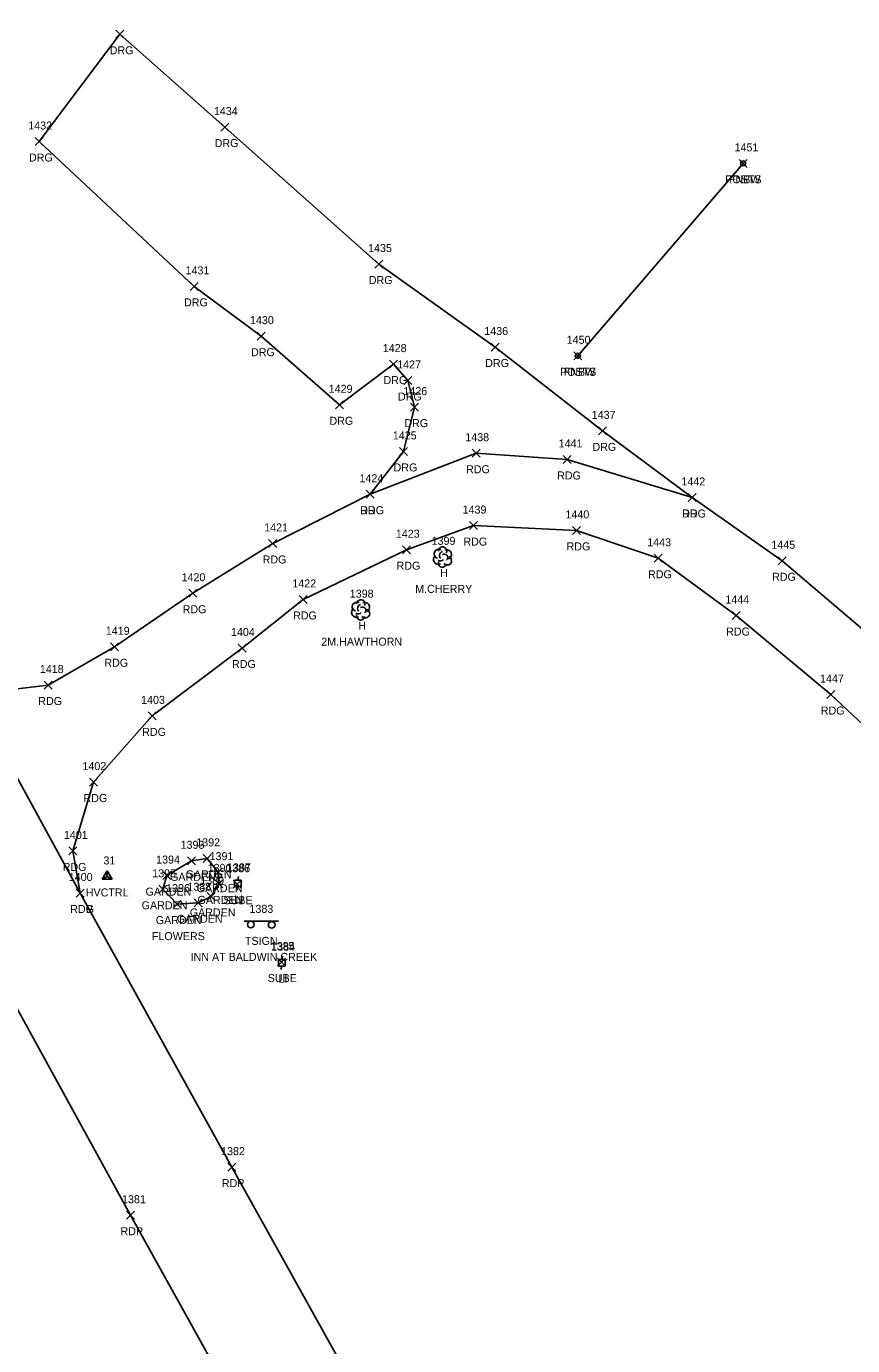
# Model space of a CAD drawing. Extents: x 1496556 to 1498241, y 599216 to 604470.
# Drawn here: x 1496878.1 to 1497084.6, y 603628.4 to 603958.1 of the extents above; entities that cross this region are included whole.
import ezdxf

# ---------------------------------------------------------------- set-up
doc = ezdxf.new("R2010")
doc.units = 0
for name, color, linetype in [('C_A', 7, 'Continuous'), ('C_I', 7, 'Continuous'), ('CPSM', 7, 'Continuous'), ('L_A', 7, 'Continuous'), ('L_C', 7, 'Continuous'), ('L_I', 7, 'Continuous'), ('L_TIC', 7, 'Continuous'), ('LAPB', 7, 'Continuous'), ('LFNC', 7, 'Continuous'), ('LPST', 7, 'Continuous'), ('LTD', 7, 'Continuous'), ('P_A', 7, 'Continuous'), ('P_I', 7, 'Continuous'), ('P_TIC', 7, 'Continuous'), ('PET', 7, 'Continuous'), ('PEU', 7, 'Continuous'), ('R_A', 7, 'Continuous'), ('R_I', 7, 'Continuous'), ('R_TIC', 7, 'Continuous'), ('RDG', 7, 'Continuous'), ('S_A', 7, 'Continuous'), ('S_C', 7, 'Continuous'), ('S_I', 7, 'Continuous'), ('SSGN', 7, 'Continuous'), ('U_A', 7, 'Continuous'), ('U_I', 7, 'Continuous'), ('U_TIC', 7, 'Continuous'), ('ULP', 7, 'Continuous')]:
    doc.layers.add(name, color=color, linetype=linetype)

msp = doc.modelspace()

# ---------------------------------------------------------------- linework, layer by layer
at = {"layer": 'CPSM'}
for p, q in [((1496896.96, 603744.93), (1496898.21, 603747.09)), ((1496896.96, 603744.93), (1496898.21, 603745.65)), ((1496899.46, 603744.93), (1496898.21, 603747.09)), ((1496898.21, 603745.65), (1496898.21, 603747.09)), ((1496898.21, 603745.65), (1496898.21, 603745.65)), ((1496898.21, 603745.65), (1496899.46, 603744.93)), ((1496896.96, 603744.93), (1496899.46, 603744.93))]:
    msp.add_line(p, q, dxfattribs=at)
at = {"layer": 'L_TIC'}
for points in [[(1497056.18, 603922.83), (1497058.18, 603924.83)], [(1497058.18, 603922.83), (1497056.18, 603924.83)], [(1497014.88, 603874.74), (1497016.88, 603876.74)], [(1497016.88, 603874.74), (1497014.88, 603876.74)], [(1496918.29, 603748.56), (1496920.29, 603750.56)], [(1496920.29, 603748.56), (1496918.29, 603750.56)], [(1496922.2, 603749.17), (1496924.2, 603751.17)], [(1496924.2, 603749.17), (1496922.2, 603751.17)], [(1496912.17, 603744.86), (1496914.17, 603746.86)], [(1496914.17, 603744.86), (1496912.17, 603746.86)], [(1496924.97, 603745.72), (1496926.97, 603747.72)], [(1496926.97, 603745.72), (1496924.97, 603747.72)], [(1496911.19, 603741.44), (1496913.19, 603743.44)], [(1496913.19, 603741.44), (1496911.19, 603743.44)], [(1496925.15, 603742.79), (1496927.15, 603744.79)], [(1496927.15, 603742.79), (1496925.15, 603744.79)], [(1496914.73, 603737.74), (1496916.73, 603739.74)], [(1496916.73, 603737.74), (1496914.73, 603739.74)], [(1496914.73, 603737.74), (1496916.73, 603739.74)], [(1496916.73, 603737.74), (1496914.73, 603739.74)], [(1496919.99, 603738.07), (1496921.99, 603740.07)], [(1496921.99, 603738.07), (1496919.99, 603740.07)], [(1496919.99, 603738.07), (1496921.99, 603740.07)], [(1496921.99, 603738.07), (1496919.99, 603740.07)], [(1496923.22, 603739.65), (1496925.22, 603741.65)], [(1496925.22, 603739.65), (1496923.22, 603741.65)]]:
    msp.add_lwpolyline(points, dxfattribs=at)
at = {"layer": 'LAPB'}
for points in [[(1496920.99, 603739.07), (1496924.22, 603740.65), (1496926.15, 603743.79), (1496925.97, 603746.72), (1496923.2, 603750.17), (1496919.29, 603749.56), (1496913.17, 603745.86), (1496912.19, 603742.44), (1496915.73, 603738.74)], [(1496920.99, 603739.07), (1496915.73, 603738.74)]]:
    msp.add_lwpolyline(points, dxfattribs=at)
at = {"layer": 'LFNC'}
msp.add_lwpolyline([(1497015.88, 603875.74), (1497057.18, 603923.83)], dxfattribs=at)
at = {"layer": 'LPST'}
for centre, radius in [((1497057.18, 603923.83), 0.625), ((1497057.18, 603923.83), 0.0833), ((1497015.88, 603875.74), 0.625), ((1497015.88, 603875.74), 0.0833)]:
    msp.add_circle(centre, radius, dxfattribs=at)
at = {"layer": 'LTD'}
for p, q in [((1496982.05, 603825.51), (1496982.05, 603825.51)), ((1496982.05, 603825.51), (1496982.05, 603825.51)), ((1496961.58, 603812.31), (1496961.58, 603812.31)), ((1496961.58, 603812.31), (1496961.58, 603812.31))]:
    msp.add_line(p, q, dxfattribs=at)
for centre in [(1496982.09, 603826.95), (1496961.62, 603813.75)]:
    msp.add_arc(centre, 1.05, 335.5272, 180.9563, dxfattribs=at)
for centre, major_axis, ratio, start_param, end_param in [((1496980.96, 603824.8), (0.58, -1.04), 0.959034, 3.141593, 6.283185), ((1496981.25, 603826.18), (1.21, -0.51), 0.895232, 1.570796, 4.712389), ((1496981.59, 603824.76), (-0.625, -0.083), 0.423636, 0, 3.141593), ((1496981.84, 603825.97), (-0.208, -0.792), 0.645439, 3.141593, 6.283185), ((1496982.55, 603825.34), (-0.5, 0.667), 0.989748, 3.141593, 6.283185), ((1496983.05, 603824.68), (-1.09, 0.79), 0.841452, 1.570796, 4.712389), ((1496983.09, 603826.09), (-1.14, -0.48), 0.949671, 1.570796, 4.712389), ((1496982.05, 603824.01), (0.26, 1.06), 0.942809, 1.570796, 4.712389), ((1496960.49, 603811.6), (0.58, -1.04), 0.959034, 3.141593, 6.283185), ((1496960.78, 603812.98), (1.21, -0.51), 0.895232, 1.570796, 4.712389), ((1496961.12, 603811.56), (-0.625, -0.083), 0.423636, 0, 3.141593), ((1496961.37, 603812.77), (-0.208, -0.792), 0.645439, 3.141593, 6.283185), ((1496962.08, 603812.15), (-0.5, 0.667), 0.989748, 3.141593, 6.283185), ((1496962.58, 603811.48), (-1.09, 0.79), 0.841452, 1.570796, 4.712389), ((1496962.62, 603812.9), (-1.14, -0.48), 0.949671, 1.570796, 4.712389), ((1496961.58, 603810.81), (0.26, 1.06), 0.942809, 1.570796, 4.712389)]:
    msp.add_ellipse(centre, major_axis=major_axis, ratio=ratio, start_param=start_param, end_param=end_param, dxfattribs=at)
at = {"layer": 'P_TIC'}
for points in [[(1496989.45, 603850.4), (1496991.45, 603852.4)], [(1496991.45, 603850.4), (1496989.45, 603852.4)], [(1497012.22, 603848.84), (1497014.22, 603850.84)], [(1497014.22, 603848.84), (1497012.22, 603850.84)], [(1496963, 603840.16), (1496965, 603842.16)], [(1496965, 603840.16), (1496963, 603842.16)], [(1497043.46, 603839.34), (1497045.46, 603841.34)], [(1497045.46, 603839.34), (1497043.46, 603841.34)], [(1496988.78, 603832.32), (1496990.78, 603834.32)], [(1496990.78, 603832.32), (1496988.78, 603834.32)], [(1497014.57, 603831.12), (1497016.57, 603833.12)], [(1497016.57, 603831.12), (1497014.57, 603833.12)], [(1496938.61, 603827.85), (1496940.61, 603829.85)], [(1496940.61, 603827.85), (1496938.61, 603829.85)], [(1496972.09, 603826.29), (1496974.09, 603828.29)], [(1496974.09, 603826.29), (1496972.09, 603828.29)], [(1497034.93, 603824.14), (1497036.93, 603826.14)], [(1497036.93, 603824.14), (1497034.93, 603826.14)], [(1497065.94, 603823.52), (1497067.94, 603825.52)], [(1497067.94, 603823.52), (1497065.94, 603825.52)], [(1496918.62, 603815.41), (1496920.62, 603817.41)], [(1496920.62, 603815.41), (1496918.62, 603817.41)], [(1496946.22, 603813.86), (1496948.22, 603815.86)], [(1496948.22, 603813.86), (1496946.22, 603815.86)], [(1497054.45, 603809.85), (1497056.45, 603811.85)], [(1497056.45, 603809.85), (1497054.45, 603811.85)], [(1496899.05, 603802.04), (1496901.05, 603804.04)], [(1496901.05, 603802.04), (1496899.05, 603804.04)], [(1496930.96, 603801.73), (1496932.96, 603803.73)], [(1496932.96, 603801.73), (1496930.96, 603803.73)], [(1496882.54, 603792.48), (1496884.54, 603794.48)], [(1496884.54, 603792.48), (1496882.54, 603794.48)], [(1497078.12, 603790.1), (1497080.12, 603792.1)], [(1497080.12, 603790.1), (1497078.12, 603792.1)], [(1496908.5, 603784.77), (1496910.5, 603786.77)], [(1496910.5, 603784.77), (1496908.5, 603786.77)], [(1496893.84, 603768.23), (1496895.84, 603770.23)], [(1496895.84, 603768.23), (1496893.84, 603770.23)], [(1496888.64, 603751.03), (1496890.64, 603753.03)], [(1496890.64, 603751.03), (1496888.64, 603753.03)], [(1496890.52, 603740.51), (1496892.52, 603742.51)], [(1496892.52, 603740.51), (1496890.52, 603742.51)], [(1496890.52, 603740.51), (1496892.52, 603742.51)], [(1496892.52, 603740.51), (1496890.52, 603742.51)], [(1496928.41, 603672.01), (1496930.41, 603674.01)], [(1496930.41, 603672.01), (1496928.41, 603674.01)], [(1496903.09, 603660), (1496905.09, 603662)], [(1496905.09, 603660), (1496903.09, 603662)]]:
    msp.add_lwpolyline(points, dxfattribs=at)
at = {"layer": 'PET'}
for points in [[(1497200.78, 603168.36), (1497190.31, 603189.95), (1497178.56, 603214.16), (1497156.38, 603259.17), (1497132.76, 603304.93), (1497107.74, 603351.81), (1497085.25, 603391.58), (1497052.51, 603451.39), (1497026.34, 603497.64), (1496978.11, 603585.44), (1496929.41, 603673.01), (1496891.52, 603741.51), (1496859.85, 603799.39), (1496832.17, 603849.95), (1496783.86, 603937.37), (1496736.46, 604023.53), (1496687.77, 604111.18), (1496657.13, 604166.72), (1496622.36, 604229.38), (1496597.22, 604275.47)], [(1497183.49, 603131.83), (1497176.45, 603149.42), (1497165.78, 603173.58), (1497153.07, 603202.24), (1497131.76, 603246.13), (1497108.09, 603291.8), (1497082.6, 603339.21), (1497060.69, 603378.6), (1497027.78, 603438.86), (1497002.63, 603483.06), (1496952.93, 603573.18), (1496904.09, 603661), (1496858.14, 603744.51), (1496836.02, 603785.33), (1496807.5, 603837.5), (1496759.38, 603924.22), (1496712.33, 604009.42), (1496662.89, 604098.73), (1496632.3, 604154.09), (1496599.03, 604214.45), (1496572.34, 604262.99)]]:
    msp.add_lwpolyline(points, dxfattribs=at)
at = {"layer": 'PEU'}
for points in [[(1496859.85, 603799.39), (1496865.05, 603796.5), (1496873.7, 603792.31), (1496883.54, 603793.48), (1496900.05, 603803.04), (1496919.62, 603816.41), (1496939.61, 603828.85), (1496964, 603841.16), (1496990.45, 603851.4), (1497013.22, 603849.84), (1497044.46, 603840.34), (1497066.94, 603824.52), (1497091.56, 603803.58), (1497125.12, 603773.26), (1497155.15, 603746.18), (1497220.12, 603687.84), (1497248.27, 603664.84), (1497294.22, 603622.27), (1497317.74, 603605), (1497324.77, 603590.17), (1497316.71, 603584.14), (1497305.64, 603569), (1497293.3, 603576.17)], [(1496891.52, 603741.51), (1496889.64, 603752.03), (1496894.84, 603769.23), (1496909.5, 603785.77), (1496931.96, 603802.73), (1496947.22, 603814.86), (1496973.09, 603827.29), (1496989.78, 603833.32), (1497015.57, 603832.12), (1497035.93, 603825.14), (1497055.45, 603810.85), (1497079.12, 603791.1), (1497113.06, 603759.28), (1497141.61, 603732.89), (1497273.63, 603619.21), (1497293.31, 603600.75), (1497297.23, 603588.2), (1497293.3, 603576.17)]]:
    msp.add_lwpolyline(points, dxfattribs=at)
at = {"layer": 'R_TIC'}
for points in [[(1496900.38, 603955.07), (1496902.38, 603957.07)], [(1496902.38, 603955.07), (1496900.38, 603957.07)], [(1496926.62, 603931.89), (1496928.62, 603933.89)], [(1496928.62, 603931.89), (1496926.62, 603933.89)], [(1496880.21, 603928.29), (1496882.21, 603930.29)], [(1496882.21, 603928.29), (1496880.21, 603930.29)], [(1496965.15, 603897.67), (1496967.15, 603899.67)], [(1496967.15, 603897.67), (1496965.15, 603899.67)], [(1496918.96, 603892.1), (1496920.96, 603894.1)], [(1496920.96, 603892.1), (1496918.96, 603894.1)], [(1496935.72, 603879.65), (1496937.72, 603881.65)], [(1496937.72, 603879.65), (1496935.72, 603881.65)], [(1496994.25, 603876.94), (1496996.25, 603878.94)], [(1496996.25, 603876.94), (1496994.25, 603878.94)], [(1496968.82, 603872.67), (1496970.82, 603874.67)], [(1496970.82, 603872.67), (1496968.82, 603874.67)], [(1496972.43, 603868.57), (1496974.43, 603870.57)], [(1496974.43, 603868.57), (1496972.43, 603870.57)], [(1496955.32, 603862.5), (1496957.32, 603864.5)], [(1496957.32, 603862.5), (1496955.32, 603864.5)], [(1496974.03, 603861.92), (1496976.03, 603863.92)], [(1496976.03, 603861.92), (1496974.03, 603863.92)], [(1497021.04, 603855.99), (1497023.04, 603857.99)], [(1497023.04, 603855.99), (1497021.04, 603857.99)], [(1496971.33, 603850.85), (1496973.33, 603852.85)], [(1496973.33, 603850.85), (1496971.33, 603852.85)], [(1496963, 603840.16), (1496965, 603842.16)], [(1496965, 603840.16), (1496963, 603842.16)], [(1497043.46, 603839.34), (1497045.46, 603841.34)], [(1497045.46, 603839.34), (1497043.46, 603841.34)]]:
    msp.add_lwpolyline(points, dxfattribs=at)
at = {"layer": 'RDG'}
msp.add_lwpolyline([(1496964, 603841.16), (1496972.33, 603851.85), (1496975.03, 603862.92), (1496973.43, 603869.57), (1496969.82, 603873.67), (1496956.32, 603863.5), (1496936.72, 603880.65), (1496919.96, 603893.1), (1496881.21, 603929.29), (1496901.38, 603956.07), (1496927.62, 603932.89), (1496966.15, 603898.67), (1496995.25, 603877.94), (1497022.04, 603856.99), (1497044.46, 603840.34)], dxfattribs=at)
at = {"layer": 'SSGN'}
for p, q in [((1496932.49, 603734.48), (1496941.08, 603734.48)), ((1496936.51, 603733.57), (1496936.51, 603733.57))]:
    msp.add_line(p, q, dxfattribs=at)
for centre in [(1496934.15, 603733.64), (1496939.36, 603733.57)]:
    msp.add_circle(centre, 0.833, dxfattribs=at)
at = {"layer": 'U_TIC'}
for points in [[(1496929.77, 603742.7), (1496931.77, 603744.7)], [(1496931.77, 603742.7), (1496929.77, 603744.7)], [(1496940.83, 603723.26), (1496942.83, 603725.26)], [(1496942.83, 603723.26), (1496940.83, 603725.26)]]:
    msp.add_lwpolyline(points, dxfattribs=at)
at = {"layer": 'ULP'}
for p, q in [((1496931.05, 603745.6), (1496930.88, 603744.76)), ((1496930.05, 603743.1), (1496930.05, 603744.76)), ((1496930.05, 603744.76), (1496931.71, 603744.76)), ((1496931.71, 603743.1), (1496930.05, 603743.1)), ((1496930.63, 603742.26), (1496930.88, 603743.1)), ((1496930.88, 603743.93), (1496930.88, 603743.93)), ((1496931.71, 603744.76), (1496931.71, 603743.1)), ((1496942.1, 603725.75), (1496941.93, 603724.92)), ((1496941.1, 603723.25), (1496941.1, 603724.92)), ((1496941.1, 603724.92), (1496942.76, 603724.92)), ((1496942.76, 603723.25), (1496941.1, 603723.25)), ((1496941.68, 603722.42), (1496941.93, 603723.25)), ((1496941.93, 603724.09), (1496941.93, 603724.09)), ((1496942.76, 603724.92), (1496942.76, 603723.25))]:
    msp.add_line(p, q, dxfattribs=at)

# ---------------------------------------------------------------- texts
at = {"layer": 'C_A'}
msp.add_text('HVCTRL', height=2, dxfattribs=at).set_placement((1496892.9, 603740.65))
at = {"layer": 'C_I'}
msp.add_text('31', height=2, dxfattribs=at).set_placement((1496897.31, 603748.65))
at = {"layer": 'L_A'}
for s, p in [('POSTS', (1497052.72, 603918.83)), ('FNBW', (1497053.65, 603918.83)), ('POSTS', (1497011.42, 603870.74)), ('FNBW', (1497012.35, 603870.74)), ('H', (1496981.48, 603820.51)), ('H', (1496961.01, 603807.31)), ('GARDEN', (1496913.96, 603744.56)), ('GARDEN', (1496917.87, 603745.17)), ('GARDEN', (1496907.84, 603740.86)), ('GARDEN', (1496920.64, 603741.72)), ('GARDEN', (1496906.86, 603737.44)), ('GARDEN', (1496920.82, 603738.79)), ('GARDEN', (1496910.4, 603733.74)), ('GARDEN', (1496910.4, 603733.74)), ('GARDEN', (1496915.66, 603734.07)), ('GARDEN', (1496915.66, 603734.07)), ('GARDEN', (1496918.89, 603735.65))]:
    msp.add_text(s, height=2, dxfattribs=at).set_placement(p)
at = {"layer": 'L_C'}
for s, p in [('M.CHERRY', (1496975.23, 603816.51)), ('2M.HAWTHORN', (1496951.76, 603803.31)), ('FLOWERS', (1496909.43, 603729.74)), ('FLOWERS', (1496909.43, 603729.74))]:
    msp.add_text(s, height=2, dxfattribs=at).set_placement(p)
at = {"layer": 'L_I'}
for s, p in [('1451', (1497055.05, 603926.83)), ('1451', (1497055.05, 603926.83)), ('1450', (1497013.1, 603878.74)), ('1450', (1497013.1, 603878.74)), ('1399', (1496979.34, 603828.51)), ('1398', (1496958.88, 603815.31)), ('1392', (1496920.51, 603753.17)), ('1393', (1496916.6, 603752.56)), ('1394', (1496910.48, 603748.86)), ('1390', (1496923.37, 603746.79)), ('1391', (1496923.84, 603749.72)), ('1395', (1496909.5, 603745.44)), ('1389', (1496921.52, 603743.65)), ('1396', (1496912.98, 603741.74)), ('1396', (1496912.98, 603741.74)), ('1388', (1496918.3, 603742.07)), ('1388', (1496918.3, 603742.07))]:
    msp.add_text(s, height=2, dxfattribs=at).set_placement(p)
at = {"layer": 'P_A'}
for s, p in [('RDG', (1496987.94, 603846.4)), ('RDG', (1497010.7, 603844.84)), ('RDG', (1496961.49, 603836.16)), ('RDG', (1497041.95, 603835.34)), ('RDG', (1496987.27, 603828.32)), ('RDG', (1497013.06, 603827.12)), ('RDG', (1496937.1, 603823.85)), ('RDG', (1496970.58, 603822.29)), ('RDG', (1497033.42, 603820.14)), ('RDG', (1497064.43, 603819.52)), ('RDG', (1496917.11, 603811.41)), ('RDG', (1496944.71, 603809.86)), ('RDG', (1497052.94, 603805.85)), ('RDG', (1496897.54, 603798.04)), ('RDG', (1496929.45, 603797.73)), ('RDG', (1496881.03, 603788.48)), ('RDG', (1497076.6, 603786.1)), ('RDG', (1496906.99, 603780.77)), ('RDG', (1496892.33, 603764.23)), ('RDG', (1496887.13, 603747.03)), ('RDG', (1496889.01, 603736.51)), ('RDP', (1496889.01, 603736.51)), ('RDP', (1496926.9, 603668.01)), ('RDP', (1496901.58, 603656))]:
    msp.add_text(s, height=2, dxfattribs=at).set_placement(p)
at = {"layer": 'P_I'}
for s, p in [('1438', (1496987.76, 603854.4)), ('1441', (1497011.09, 603852.84)), ('1424', (1496961.31, 603844.16)), ('1442', (1497041.77, 603843.34)), ('1439', (1496987.08, 603836.32)), ('1440', (1497012.79, 603835.12)), ('1421', (1496937.49, 603831.85)), ('1423', (1496970.4, 603830.29)), ('1443', (1497033.23, 603828.14)), ('1445', (1497064.25, 603827.52)), ('1420', (1496916.84, 603819.41)), ('1422', (1496944.53, 603817.86)), ('1444', (1497052.75, 603813.85)), ('1419', (1496897.91, 603806.04)), ('1404', (1496929.19, 603805.73)), ('1418', (1496881.42, 603796.48)), ('1447', (1497076.42, 603794.1)), ('1403', (1496906.73, 603788.77)), ('1402', (1496892.07, 603772.23)), ('1401', (1496887.43, 603755.03)), ('1400', (1496888.66, 603744.51)), ('1400', (1496888.66, 603744.51)), ('1382', (1496926.72, 603676.01)), ('1381', (1496901.96, 603664))]:
    msp.add_text(s, height=2, dxfattribs=at).set_placement(p)
at = {"layer": 'R_A'}
for p in [(1496898.87, 603951.07), (1496925.11, 603927.89), (1496878.7, 603924.29), (1496963.64, 603893.67), (1496917.45, 603888.1), (1496934.2, 603875.65), (1496992.73, 603872.94), (1496967.31, 603868.67), (1496970.92, 603864.57), (1496953.8, 603858.5), (1496972.52, 603857.92), (1497019.53, 603851.99), (1496969.82, 603846.85), (1496961.49, 603836.16), (1497041.95, 603835.34)]:
    msp.add_text('DRG', height=2, dxfattribs=at).set_placement(p)
at = {"layer": 'R_I'}
for s, p in [('1434', (1496924.92, 603935.89)), ('1432', (1496878.52, 603932.29)), ('1435', (1496963.46, 603901.67)), ('1431', (1496917.83, 603896.1)), ('1430', (1496933.94, 603883.65)), ('1436', (1496992.5, 603880.94)), ('1428', (1496967.13, 603876.67)), ('1427', (1496970.74, 603872.57)), ('1429', (1496953.61, 603866.5)), ('1426', (1496972.28, 603865.92)), ('1437', (1497019.35, 603859.99)), ('1425', (1496969.64, 603854.85)), ('1424', (1496961.31, 603844.16)), ('1442', (1497041.77, 603843.34))]:
    msp.add_text(s, height=2, dxfattribs=at).set_placement(p)
at = {"layer": 'S_A'}
msp.add_text('TSIGN', height=2, dxfattribs=at).set_placement((1496932.68, 603728.55))
at = {"layer": 'S_C'}
msp.add_text('INN AT BALDWIN CREEK', height=2, dxfattribs=at).set_placement((1496919.1, 603724.55))
at = {"layer": 'S_I'}
msp.add_text('1383', height=2, dxfattribs=at).set_placement((1496933.81, 603736.55))
at = {"layer": 'U_A'}
for s, p in [('SUBE', (1496927.31, 603738.7)), ('LI', (1496929.98, 603738.93)), ('SUBE', (1496938.36, 603719.26)), ('LI', (1496941.03, 603719.09))]:
    msp.add_text(s, height=2, dxfattribs=at).set_placement(p)
at = {"layer": 'U_I'}
for s, p in [('1386', (1496928.02, 603746.7)), ('1387', (1496928.19, 603746.93)), ('1385', (1496939.13, 603727.26)), ('1384', (1496939.24, 603727.09))]:
    msp.add_text(s, height=2, dxfattribs=at).set_placement(p)

doc.saveas('drawing.dxf')
